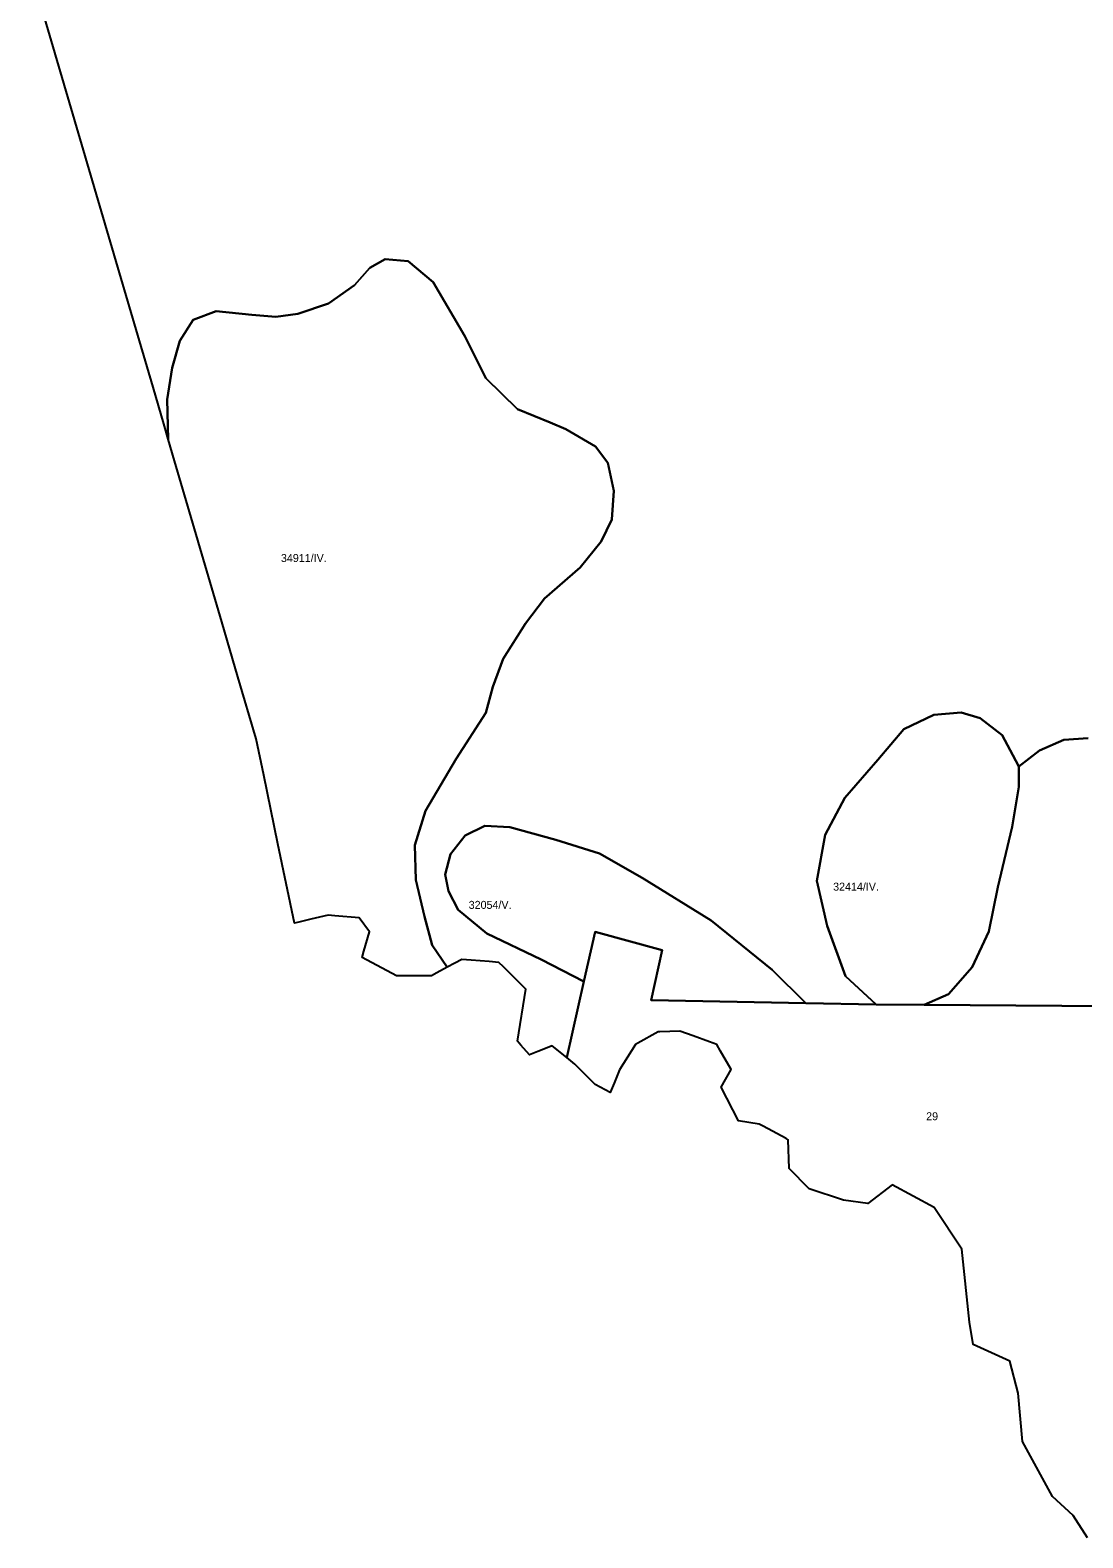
# Model space of a CAD drawing. Extents: x -521621 to -516761, y -1190184 to -1184927.
# Drawn here: x -521384 to -520857, y -1188846 to -1188092 of the extents above; entities that cross this region are included whole.
import ezdxf

# ---------------------------------------------------------------- set-up
doc = ezdxf.new("R2010")
doc.units = 0
doc.layers.add('BPEJ_s', color=7, linetype='Continuous')

msp = doc.modelspace()

# ---------------------------------------------------------------- linework, layer by layer
at = {"layer": 'BPEJ_s'}
for points in [[(-520854.73, -1188446.42), (-520866.76, -1188447.19), (-520879.05, -1188452.57), (-520889.29, -1188460.51), (-520892.36, -1188454.87), (-520897.74, -1188444.88), (-520908.74, -1188436.43), (-520918.22, -1188433.61), (-520931.78, -1188434.64), (-520946.89, -1188441.81), (-520959.94, -1188457.18), (-520976.33, -1188476.14), (-520986.23, -1188494.72), (-520990.39, -1188517.77), (-520985.27, -1188540.18), (-520975.99, -1188565.47), (-520960.73, -1188579.64), (-520995.82, -1188578.94), (-521012.79, -1188562.27), (-521043.18, -1188537.62), (-521077.74, -1188516.17), (-521099.17, -1188504.01), (-521120.93, -1188497.28), (-521143.96, -1188490.88), (-521156.44, -1188490.24), (-521166.36, -1188495.04), (-521173.72, -1188504.32), (-521176.28, -1188514.57), (-521174.68, -1188522.89), (-521169.88, -1188532.18), (-521155.48, -1188544.02), (-521128.29, -1188557.15), (-521106.94, -1188568.13), (-521115.49, -1188606.17), (-521122.78, -1188600.2), (-521130.05, -1188603.14), (-521134.11, -1188604.78), (-521138.42, -1188599.87), (-521140.13, -1188597.92), (-521136.03, -1188571.95), (-521140.8, -1188567.17), (-521147.19, -1188560.77), (-521149.41, -1188558.54), (-521154.35, -1188558.13), (-521163.27, -1188557.4), (-521168.04, -1188557.01), (-521171.45, -1188558.87), (-521175.31, -1188560.97), (-521182.82, -1188549.95), (-521186.66, -1188535.53), (-521190.98, -1188517.26), (-521191.46, -1188499.96), (-521186.18, -1188482.66), (-521170.81, -1188456.7), (-521155.92, -1188433.63), (-521152.55, -1188420.65), (-521147.27, -1188406.71), (-521136.22, -1188388.93), (-521126.62, -1188376.43), (-521108.84, -1188361.05), (-521098.27, -1188348.07), (-521092.99, -1188337.02), (-521092.03, -1188322.6), (-521094.91, -1188308.66), (-521101.16, -1188300.49), (-521116.05, -1188291.84), (-521123.73, -1188288.48), (-521140.07, -1188281.75), (-521155.92, -1188266.36), (-521166.48, -1188245.22), (-521182.34, -1188218.3), (-521194.82, -1188207.73), (-521206.35, -1188206.76), (-521214.04, -1188211.09), (-521221.72, -1188219.74), (-521234.69, -1188228.87), (-521250.06, -1188234.16), (-521261.11, -1188235.6), (-521273.12, -1188234.64), (-521290.89, -1188232.72), (-521302.42, -1188237.05), (-521309.15, -1188247.62), (-521312.99, -1188261.08), (-521315.39, -1188276.94), (-521314.88, -1188296.72), (-521317.08, -1188289.21), (-521322.47, -1188270.71), (-521329.32, -1188247.56), (-521339.28, -1188213.59), (-521383.96, -1188061.22)], [(-520821.97, -1188580.54), (-520936.76, -1188579.79), (-520924.48, -1188574.44), (-520912.64, -1188560.99), (-520904.33, -1188543.06), (-520899.85, -1188520.97), (-520892.62, -1188490.74), (-520889.29, -1188470.76), (-520889.29, -1188460.51), (-520879.05, -1188452.57), (-520866.76, -1188447.19), (-520854.73, -1188446.42)], [(-520854.95, -1188846.39), (-520862.19, -1188835.28), (-520872.44, -1188825.71), (-520887.53, -1188798.17), (-520889.67, -1188774.08), (-520893.83, -1188757.95), (-520912.11, -1188749.64), (-520914.06, -1188738.43), (-520917.86, -1188702.05), (-520931.64, -1188681.13), (-520952.74, -1188669.81), (-520964.84, -1188679.13), (-520977.08, -1188677.44), (-520994.15, -1188671.81), (-521004.27, -1188661.63), (-521004.69, -1188647.25), (-521005.77, -1188646.66), (-521017.32, -1188640.41), (-521019.17, -1188639.41), (-521029.65, -1188637.81), (-521038.21, -1188620.89), (-521033.27, -1188612.17), (-521038.52, -1188602.98), (-521040.47, -1188599.56), (-521044.07, -1188598.25), (-521052.33, -1188595.25), (-521058.93, -1188592.86), (-521068.86, -1188593.28), (-521069.75, -1188593.32), (-521079.91, -1188598.99), (-521081.11, -1188599.66), (-521089.04, -1188612.26), (-521091.86, -1188618.97), (-521093.82, -1188623.63), (-521101.22, -1188619.68), (-521109.92, -1188611), (-521111.46, -1188609.47), (-521115.49, -1188606.17), (-521106.94, -1188568.13), (-521101.34, -1188543.21), (-521067.77, -1188552.46), (-521073.29, -1188577.4), (-520995.82, -1188578.94), (-520960.73, -1188579.64), (-520936.76, -1188579.79), (-520821.97, -1188580.54)]]:
    msp.add_lwpolyline(points, dxfattribs=at)
for points in [[(-521314.88, -1188296.72), (-521315.39, -1188276.94), (-521312.99, -1188261.08), (-521309.15, -1188247.62), (-521302.42, -1188237.05), (-521290.89, -1188232.72), (-521273.12, -1188234.64), (-521261.11, -1188235.6), (-521250.06, -1188234.16), (-521234.69, -1188228.87), (-521221.72, -1188219.74), (-521214.04, -1188211.09), (-521206.35, -1188206.76), (-521194.82, -1188207.73), (-521182.34, -1188218.3), (-521166.48, -1188245.22), (-521155.92, -1188266.36), (-521140.07, -1188281.75), (-521123.73, -1188288.48), (-521116.05, -1188291.84), (-521101.16, -1188300.49), (-521094.91, -1188308.66), (-521092.03, -1188322.6), (-521092.99, -1188337.02), (-521098.27, -1188348.07), (-521108.84, -1188361.05), (-521126.62, -1188376.43), (-521136.22, -1188388.93), (-521147.27, -1188406.71), (-521152.55, -1188420.65), (-521155.92, -1188433.63), (-521170.81, -1188456.7), (-521186.18, -1188482.66), (-521191.46, -1188499.96), (-521190.98, -1188517.26), (-521186.66, -1188535.53), (-521182.82, -1188549.95), (-521175.31, -1188560.97), (-521180.43, -1188563.76), (-521183.18, -1188565.26), (-521200.64, -1188565.26), (-521217.86, -1188556.05), (-521216.97, -1188552.88), (-521214.26, -1188543.22), (-521219.43, -1188536.24), (-521231.51, -1188535.19), (-521234.93, -1188534.89), (-521237.09, -1188535.42), (-521243.51, -1188536.99), (-521248.89, -1188538.31), (-521251.65, -1188538.99), (-521259.97, -1188499.15), (-521267.12, -1188464.93), (-521270.92, -1188446.71), (-521280.04, -1188415.62), (-521288.07, -1188388.22), (-521311.68, -1188307.7)], [(-520960.73, -1188579.64), (-520975.99, -1188565.47), (-520985.27, -1188540.18), (-520990.39, -1188517.77), (-520986.23, -1188494.72), (-520976.33, -1188476.14), (-520959.94, -1188457.18), (-520946.89, -1188441.81), (-520931.78, -1188434.64), (-520918.22, -1188433.61), (-520908.74, -1188436.43), (-520897.74, -1188444.88), (-520892.36, -1188454.87), (-520889.29, -1188460.51), (-520889.29, -1188470.76), (-520892.62, -1188490.74), (-520899.85, -1188520.97), (-520904.33, -1188543.06), (-520912.64, -1188560.99), (-520924.48, -1188574.44), (-520936.76, -1188579.79)], [(-521106.94, -1188568.13), (-521128.29, -1188557.15), (-521155.48, -1188544.02), (-521169.88, -1188532.18), (-521174.68, -1188522.89), (-521176.28, -1188514.57), (-521173.72, -1188504.32), (-521166.36, -1188495.04), (-521156.44, -1188490.24), (-521143.96, -1188490.88), (-521120.93, -1188497.28), (-521099.17, -1188504.01), (-521077.74, -1188516.17), (-521043.18, -1188537.62), (-521012.79, -1188562.27), (-520995.82, -1188578.94), (-521073.29, -1188577.4), (-521067.77, -1188552.46), (-521101.34, -1188543.21)]]:
    msp.add_lwpolyline(points, close=True, dxfattribs=at)

# ---------------------------------------------------------------- texts
for s, p in [('34911/IV.', (-521258.49, -1188358.25)), ('32414/IV.', (-520982.24, -1188522.65)), ('32054/V.', (-521164.56, -1188531.76)), ('29', (-520935.69, -1188637.51))]:
    msp.add_text(s, height=4, dxfattribs=at).set_placement(p)

doc.saveas('drawing.dxf')
